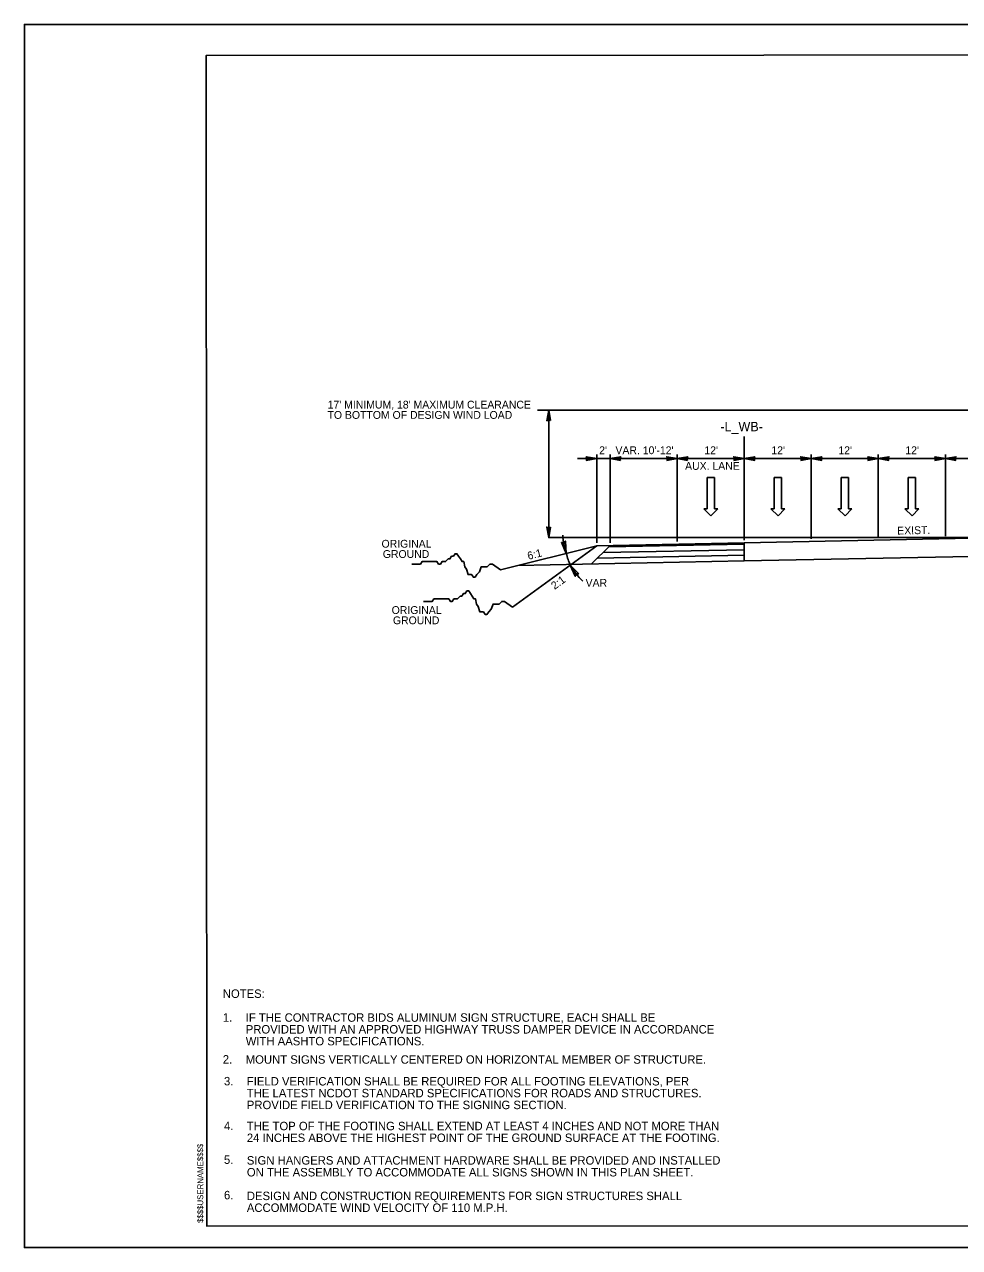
# Model space of a CAD drawing. Extents: x 1725232 to 1728895, y 538685 to 540544.
# Drawn here: x 1725232.3 to 1725399.8, y 539295.4 to 539514.6 of the extents above; entities that cross this region are included whole.
import ezdxf

# ---------------------------------------------------------------- set-up
doc = ezdxf.new("R2010")
doc.units = 0
for name, color, linetype in [('Default', 7, 'Continuous'), ('DEV BORDER CELL', 7, 'Continuous'), ('Overhead Sheet Border', 7, 'Continuous'), ('Overhead Sheet Text', 7, 'Continuous'), ('Prop Dimension Text', 7, 'Continuous'), ('Sheet Plot Border Outside CELL', 7, 'Continuous'), ('Typical Hinge Slope Interstate CELL', 7, 'Continuous'), ('Typical Pavement Slope CELL', 7, 'Continuous'), ('Typical Pavement Slope Information CELL', 7, 'Continuous'), ('Typical Text Centerline CELL', 7, 'Continuous')]:
    doc.layers.add(name, color=color, linetype=linetype)

msp = doc.modelspace()

# ---------------------------------------------------------------- linework, layer by layer
at = {"layer": 'Default'}
for p, q in [((1725326.2, 539445.43), (1725324.2, 539445.43)), ((1725326.2, 539422.6), (1725326.2, 539445.43)), ((1725326.2, 539445.43), (1725439.14, 539445.43)), ((1725361.24, 539422.16), (1725361.24, 539440.74)), ((1725334.82, 539421.68), (1725334.82, 539437.48)), ((1725337.22, 539421.68), (1725337.22, 539437.48)), ((1725349.23, 539421.92), (1725349.23, 539437.48)), ((1725361.24, 539422.16), (1725361.24, 539437.48)), ((1725373.25, 539422.4), (1725373.25, 539437.48)), ((1725385.28, 539422.64), (1725385.28, 539437.48)), ((1725397.29, 539422.88), (1725397.29, 539437.48)), ((1725331.37, 539436.74), (1725337.24, 539436.74)), ((1725337.22, 539421.68), (1725337.22, 539437.24)), ((1725337.24, 539436.74), (1725349.25, 539436.74)), ((1725349.25, 539436.74), (1725361.26, 539436.74)), ((1725361.26, 539436.74), (1725373.27, 539436.74)), ((1725373.27, 539436.74), (1725385.28, 539436.74)), ((1725385.28, 539436.74), (1725397.29, 539436.74)), ((1725397.29, 539436.74), (1725408.09, 539436.74)), ((1725354.61, 539427.76), (1725354.61, 539433.36)), ((1725354.61, 539433.36), (1725355.93, 539433.36)), ((1725355.93, 539433.36), (1725355.93, 539427.76)), ((1725366.62, 539427.76), (1725366.62, 539433.36)), ((1725366.62, 539433.36), (1725367.94, 539433.36)), ((1725367.94, 539433.36), (1725367.94, 539427.76)), ((1725378.63, 539427.76), (1725378.63, 539433.36)), ((1725378.63, 539433.36), (1725379.95, 539433.36)), ((1725379.95, 539433.36), (1725379.95, 539427.76)), ((1725390.64, 539427.76), (1725390.64, 539433.36)), ((1725390.64, 539433.36), (1725391.96, 539433.36)), ((1725391.96, 539433.36), (1725391.96, 539427.76)), ((1725355.29, 539426.5), (1725354.01, 539427.76)), ((1725354.01, 539427.76), (1725354.61, 539427.76)), ((1725356.53, 539427.76), (1725355.29, 539426.5)), ((1725355.93, 539427.76), (1725356.53, 539427.76)), ((1725367.3, 539426.5), (1725366.02, 539427.76)), ((1725366.02, 539427.76), (1725366.62, 539427.76)), ((1725368.54, 539427.76), (1725367.3, 539426.5)), ((1725367.94, 539427.76), (1725368.54, 539427.76)), ((1725379.31, 539426.5), (1725378.03, 539427.76)), ((1725378.03, 539427.76), (1725378.63, 539427.76)), ((1725380.55, 539427.76), (1725379.31, 539426.5)), ((1725379.95, 539427.76), (1725380.55, 539427.76)), ((1725391.32, 539426.5), (1725390.04, 539427.76)), ((1725390.04, 539427.76), (1725390.64, 539427.76)), ((1725392.56, 539427.76), (1725391.32, 539426.5)), ((1725391.96, 539427.76), (1725392.56, 539427.76)), ((1725408.09, 539422.6), (1725326.2, 539422.6))]:
    msp.add_line(p, q, dxfattribs=at)
for points in [[(1725326.52, 539443.55), (1725326.2, 539445.43), (1725325.87, 539443.54), (1725326.2, 539443.78)], [(1725332.95, 539436.42), (1725334.82, 539436.74), (1725332.93, 539437.07), (1725333.17, 539436.74)], [(1725339.1, 539436.42), (1725337.22, 539436.74), (1725339.11, 539437.07), (1725338.87, 539436.74)], [(1725347.36, 539436.42), (1725349.23, 539436.74), (1725347.35, 539437.07), (1725347.59, 539436.74)], [(1725351.11, 539436.42), (1725349.23, 539436.74), (1725351.12, 539437.07), (1725350.88, 539436.74)], [(1725359.37, 539436.42), (1725361.24, 539436.74), (1725359.36, 539437.07), (1725359.6, 539436.74)], [(1725363.12, 539436.42), (1725361.24, 539436.74), (1725363.13, 539437.07), (1725362.89, 539436.74)], [(1725371.38, 539436.42), (1725373.25, 539436.74), (1725371.37, 539437.07), (1725371.6, 539436.74)], [(1725375.13, 539436.42), (1725373.25, 539436.74), (1725375.14, 539437.07), (1725374.9, 539436.74)], [(1725383.41, 539436.42), (1725385.28, 539436.74), (1725383.4, 539437.07), (1725383.64, 539436.74)], [(1725387.16, 539436.42), (1725385.28, 539436.74), (1725387.17, 539437.07), (1725386.93, 539436.74)], [(1725395.42, 539436.42), (1725397.29, 539436.74), (1725395.41, 539437.07), (1725395.65, 539436.74)], [(1725399.17, 539436.42), (1725397.29, 539436.74), (1725399.18, 539437.07), (1725398.94, 539436.74)], [(1725326.52, 539424.48), (1725326.2, 539422.6), (1725325.87, 539424.49), (1725326.2, 539424.25)], [(1725328.47, 539421.78), (1725329.36, 539419.77), (1725329.2, 539421.98), (1725328.9, 539421.61)], [(1725331.58, 539416.09), (1725330.07, 539417.68), (1725330.95, 539415.66), (1725331.12, 539416.1)], [(1725331.58, 539416.09), (1725330.07, 539417.68), (1725330.95, 539415.66), (1725331.12, 539416.1)]]:
    msp.add_lwpolyline(points, close=True, dxfattribs=at)
at = {"layer": 'DEV BORDER CELL'}
msp.add_line((1725232.26, 539514.55), (1725232.26, 539514.55), dxfattribs=at)
at = {"layer": 'Overhead Sheet Border'}
msp.add_lwpolyline([(1725564.58, 539509.16), (1725264.83, 539509), (1725264.95, 539299.17), (1725564.7, 539299.33)], close=True, dxfattribs=at)
at = {"layer": 'Sheet Plot Border Outside CELL'}
msp.add_lwpolyline([(1725568.84, 539514.55), (1725232.26, 539514.55), (1725232.26, 539295.37), (1725568.84, 539295.37)], close=True, dxfattribs=at)
at = {"layer": 'Typical Hinge Slope Interstate CELL'}
for points in [[(1725317.58, 539416.83), (1725316.13, 539417.84), (1725315.67, 539417.84), (1725315.2, 539417.38), (1725314.89, 539417.38), (1725314.42, 539417.38), (1725314.11, 539417.38), (1725313.8, 539416.44), (1725313.33, 539415.97), (1725313.02, 539415.5), (1725312.71, 539415.5), (1725312.4, 539415.97), (1725312.08, 539415.97), (1725311.77, 539415.97), (1725311.46, 539416.91), (1725311.15, 539417.38), (1725310.99, 539418.31), (1725310.68, 539418.31), (1725310.37, 539418.78), (1725310.06, 539419.24), (1725309.75, 539419.71), (1725309.44, 539419.71), (1725309.12, 539419.24), (1725308.81, 539419.24), (1725308.5, 539418.78), (1725308.19, 539418.78), (1725307.72, 539418.31), (1725307.41, 539418.31), (1725307.1, 539418.31), (1725306.79, 539417.84), (1725306.48, 539417.84), (1725306.17, 539418.31), (1725305.85, 539418.31), (1725305.54, 539418.31), (1725305.23, 539418.31), (1725304.92, 539418.31), (1725304.45, 539418.31), (1725303.99, 539418.31), (1725303.52, 539418.31), (1725303.21, 539417.84), (1725302.74, 539417.84), (1725302.27, 539417.84), (1725301.65, 539417.84)], [(1725319.7, 539410.14), (1725318.26, 539411.15), (1725317.79, 539411.15), (1725317.32, 539410.69), (1725317.01, 539410.69), (1725316.54, 539410.69), (1725316.23, 539410.69), (1725315.92, 539409.75), (1725315.45, 539409.28), (1725315.14, 539408.82), (1725314.83, 539408.82), (1725314.52, 539409.28), (1725314.21, 539409.28), (1725313.89, 539409.28), (1725313.58, 539410.22), (1725313.27, 539410.69), (1725313.11, 539411.62), (1725312.8, 539411.62), (1725312.49, 539412.09), (1725312.18, 539412.56), (1725311.87, 539413.03), (1725311.56, 539413.03), (1725311.25, 539412.56), (1725310.93, 539412.56), (1725310.62, 539412.09), (1725310.31, 539412.09), (1725309.84, 539411.62), (1725309.53, 539411.62), (1725309.22, 539411.62), (1725308.91, 539411.15), (1725308.6, 539411.15), (1725308.29, 539411.62), (1725307.98, 539411.62), (1725307.66, 539411.62), (1725307.35, 539411.62), (1725307.04, 539411.62), (1725306.57, 539411.62), (1725306.11, 539411.62), (1725305.64, 539411.62), (1725305.33, 539411.15), (1725304.86, 539411.15), (1725304.39, 539411.15), (1725303.77, 539411.15)]]:
    msp.add_lwpolyline(points, dxfattribs=at)
for centre, start, end in [((1725340.79, 539423.64), 182.9343, 198.686), ((1725340.62, 539423.55), 209.0778, 226.6941), ((1725340.62, 539423.55), 209.0778, 226.6941)]:
    msp.add_arc(centre, 12.07, start, end, dxfattribs=at)
msp.add_ellipse((1725335.14, 539426.66), major_axis=(-1.85, -11.93), ratio=0.5, start_param=5.403228, end_param=5.638322, dxfattribs=at)
at = {"layer": 'Typical Pavement Slope CELL'}
for p, q in [((1725361.24, 539421.67), (1725408.09, 539422.6)), ((1725334.82, 539421.14), (1725317.58, 539416.83)), ((1725334.82, 539421.14), (1725319.7, 539410.14)), ((1725337.22, 539421.19), (1725333.9, 539417.87)), ((1725334.82, 539421.14), (1725361.24, 539421.67)), ((1725335.95, 539419.91), (1725361.24, 539420.42)), ((1725336.97, 539420.93), (1725361.24, 539421.42)), ((1725361.24, 539418.42), (1725361.24, 539421.67)), ((1725320.68, 539417.6), (1725361.24, 539418.42)), ((1725334.93, 539418.89), (1725361.24, 539419.42)), ((1725361.24, 539418.42), (1725408.09, 539419.35))]:
    msp.add_line(p, q, dxfattribs=at)

# ---------------------------------------------------------------- texts
at = {"layer": 'Overhead Sheet Text'}
for s, height, p in [('NOTES:', 1.513, (1725267.8, 539340.11)), ('1.', 1.513, (1725267.8, 539335.83)), ('IF THE CONTRACTOR BIDS ALUMINUM SIGN STRUCTURE, EACH SHALL BE ', 1.5129, (1725271.91, 539335.83)), ('PROVIDED WITH AN APPROVED HIGHWAY TRUSS DAMPER DEVICE IN ACCORDANCE', 1.5129, (1725271.91, 539333.72)), ('WITH AASHTO SPECIFICATIONS.', 1.5129, (1725271.91, 539331.6)), ('2.', 1.513, (1725267.8, 539328.33)), ('MOUNT SIGNS VERTICALLY CENTERED ON HORIZONTAL MEMBER OF STRUCTURE.', 1.5129, (1725271.91, 539328.31)), ('3.', 1.513, (1725268.01, 539324.43)), ('FIELD VERIFICATION SHALL BE REQUIRED FOR ALL FOOTING ELEVATIONS, PER', 1.5129, (1725272.11, 539324.41)), ('THE LATEST NCDOT STANDARD SPECIFICATIONS FOR ROADS AND STRUCTURES.', 1.5129, (1725272.11, 539322.29)), ('PROVIDE FIELD VERIFICATION TO THE SIGNING SECTION.', 1.5129, (1725272.11, 539320.17)), ('4.', 1.513, (1725268.01, 539316.41)), ('THE TOP OF THE FOOTING SHALL EXTEND AT LEAST 4 INCHES AND NOT MORE THAN', 1.5129, (1725272.11, 539316.39)), ('24 INCHES ABOVE THE HIGHEST POINT OF THE GROUND SURFACE AT THE FOOTING.', 1.5129, (1725272.11, 539314.28)), ('5.', 1.513, (1725268.01, 539310.36)), ('SIGN HANGERS AND ATTACHMENT HARDWARE SHALL BE PROVIDED AND INSTALLED ', 1.5129, (1725272.11, 539310.23)), ('ON THE ASSEMBLY TO ACCOMMODATE ALL SIGNS SHOWN IN THIS PLAN SHEET.', 1.5129, (1725272.11, 539308.11)), ('6.', 1.513, (1725268.01, 539304.01)), ('DESIGN AND CONSTRUCTION REQUIREMENTS FOR SIGN STRUCTURES SHALL', 1.5129, (1725272.11, 539303.87)), ('ACCOMMODATE WIND VELOCITY OF 110 M.P.H.', 1.5129, (1725272.11, 539301.75))]:
    msp.add_text(s, height=height, dxfattribs=at).set_placement(p)
msp.add_text('$$$$USERNAME$$$$', height=1.0491, rotation=90.0308, dxfattribs=at).set_placement((1725264.29, 539299.78))
at = {"layer": 'Prop Dimension Text'}
for s, height, p in [("17' MINIMUM, 18' MAXIMUM CLEARANCE", 1.4011, (1725286.59, 539445.72)), ('TO BOTTOM OF DESIGN WIND LOAD', 1.4011, (1725286.57, 539443.88)), ('ORIGINAL', 1.401, (1725296.25, 539420.79)), ('GROUND', 1.401, (1725296.48, 539418.95)), ('VAR', 1.401, (1725332.82, 539413.78)), ('ORIGINAL', 1.401, (1725298.06, 539408.91)), ('GROUND', 1.401, (1725298.29, 539407.07))]:
    msp.add_text(s, height=height, dxfattribs=at).set_placement(p)
for s, rotation, p in [('6:1', 14.0362, (1725322.58, 539418.61)), ('2:1', 36.0298, (1725327.26, 539413.21))]:
    msp.add_text(s, height=1.401, rotation=rotation, dxfattribs=at).set_placement(p)
at = {"layer": 'Typical Pavement Slope Information CELL'}
for s, height, p in [("2'", 1.401, (1725335.25, 539437.54)), ("VAR. 10'-12'", 1.4011, (1725338.17, 539437.54)), ("12'", 1.401, (1725354.1, 539437.54)), ("12'", 1.401, (1725366.11, 539437.54)), ("12'", 1.401, (1725378.12, 539437.54)), ("12'", 1.401, (1725390.12, 539437.54)), ('AUX. LANE', 1.401, (1725350.65, 539434.74))]:
    msp.add_text(s, height=height, dxfattribs=at).set_placement(p)
msp.add_text('EXIST.', height=1.401, rotation=1.1457, dxfattribs=at).set_placement((1725388.68, 539423.14))
at = {"layer": 'Typical Text Centerline CELL'}
msp.add_text('-L_WB-', height=1.684, dxfattribs=at).set_placement((1725356.96, 539441.65))

doc.saveas('drawing.dxf')
